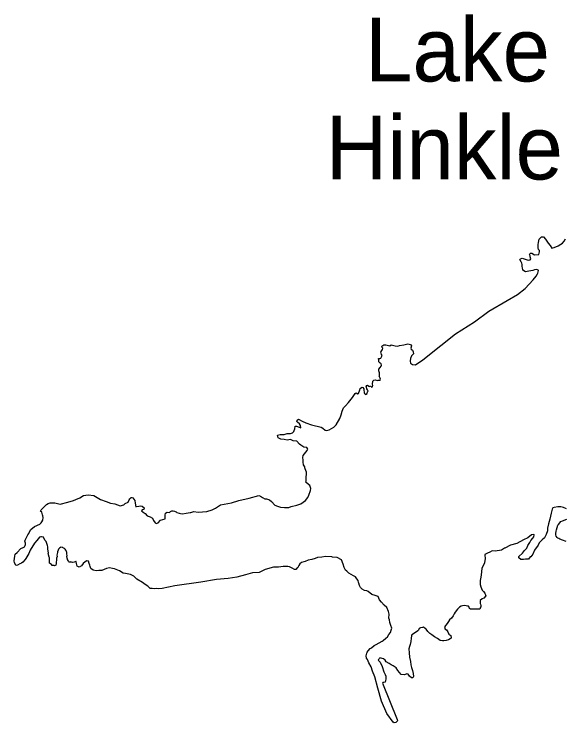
# Model space of a CAD drawing. Extents: x 1382482 to 1385815, y 1168351 to 1170484.
# Drawn here: x 1382760.2 to 1382805.8, y 1169935.8 to 1169994.4 of the extents above; entities that cross this region are included whole.
import ezdxf

# ---------------------------------------------------------------- set-up
doc = ezdxf.new("R2010")
doc.units = 0
doc.layers.add('9', color=7, linetype='Continuous')

msp = doc.modelspace()

# ---------------------------------------------------------------- linework, layer by layer
at = {"layer": '9'}
for points in [[(1382793.162, 1169965.416), (1382793.411, 1169965.4), (1382794.003, 1169965.81), (1382795.489, 1169966.995), (1382796.72, 1169967.945), (1382798.269, 1169968.951), (1382799.461, 1169969.84), (1382800.973, 1169970.715), (1382801.832, 1169971.199), (1382802.462, 1169971.71), (1382803.139, 1169972.411), (1382803.393, 1169972.725), (1382803.49, 1169972.927), (1382803.509, 1169972.977), (1382803.537, 1169973.068), (1382803.585, 1169973.178), (1382803.545, 1169973.228), (1382803.434, 1169973.266), (1382803.235, 1169973.233), (1382803.107, 1169973.181), (1382802.937, 1169973.168), (1382802.788, 1169973.145), (1382802.629, 1169973.113), (1382802.49, 1169973.08), (1382802.279, 1169973.217), (1382802.278, 1169973.267), (1382802.246, 1169973.396), (1382802.233, 1169973.556), (1382802.221, 1169973.676), (1382802.189, 1169973.806), (1382802.128, 1169973.895), (1382802.025, 1169974.103), (1382802.084, 1169974.144), (1382802.223, 1169974.196), (1382802.463, 1169974.13), (1382802.734, 1169974.045), (1382802.893, 1169974.077), (1382802.951, 1169974.168), (1382802.899, 1169974.327), (1382802.888, 1169974.397), (1382802.836, 1169974.516), (1382802.845, 1169974.576), (1382802.914, 1169974.628), (1382803.034, 1169974.62), (1382803.245, 1169974.483), (1382803.604, 1169974.519), (1382803.67, 1169974.72), (1382803.648, 1169974.83), (1382803.567, 1169974.938), (1382803.535, 1169975.058), (1382803.543, 1169975.178), (1382803.551, 1169975.328), (1382803.578, 1169975.509), (1382803.623, 1169975.769), (1382803.81, 1169975.972), (1382803.989, 1169975.965), (1382804.142, 1169975.788), (1382804.366, 1169975.462), (1382804.529, 1169975.244), (1382804.692, 1169975.047), (1382804.881, 1169975.09), (1382805.197, 1169975.225), (1382805.415, 1169975.359), (1382805.553, 1169975.451), (1382805.69, 1169975.613), (1382805.806, 1169975.805)], [(1382786.645, 1169960.229), (1382786.851, 1169960.442), (1382787.142, 1169960.957), (1382787.247, 1169961.249), (1382787.322, 1169961.55), (1382787.457, 1169961.842), (1382787.624, 1169962.005), (1382787.868, 1169962.279), (1382788.191, 1169962.704), (1382788.415, 1169963.028), (1382788.504, 1169963.079), (1382788.625, 1169962.981), (1382788.694, 1169963.032), (1382788.789, 1169963.324), (1382788.827, 1169963.425), (1382788.945, 1169963.527), (1382788.975, 1169963.537), (1382789.045, 1169963.518), (1382789.116, 1169963.409), (1382789.139, 1169963.27), (1382789.16, 1169963.17), (1382789.161, 1169963.1), (1382789.182, 1169963.021), (1382789.263, 1169962.952), (1382789.392, 1169963.014), (1382789.44, 1169963.155), (1382789.499, 1169963.206), (1382789.427, 1169963.315), (1382789.366, 1169963.414), (1382789.354, 1169963.533), (1382789.332, 1169963.613), (1382789.371, 1169963.694), (1382789.431, 1169963.705), (1382789.541, 1169963.636), (1382789.602, 1169963.607), (1382789.701, 1169963.649), (1382789.772, 1169963.54), (1382789.831, 1169963.581), (1382789.87, 1169963.692), (1382789.858, 1169963.802), (1382789.884, 1169964.052), (1382789.942, 1169964.133), (1382790.102, 1169964.146), (1382790.232, 1169964.098), (1382790.301, 1169964.119), (1382790.481, 1169964.132), (1382790.509, 1169964.212), (1382790.488, 1169964.302), (1382790.406, 1169964.461), (1382790.416, 1169964.461), (1382790.415, 1169964.481), (1382790.433, 1169964.611), (1382790.421, 1169964.731), (1382790.4, 1169964.811), (1382790.369, 1169964.89), (1382790.357, 1169964.98), (1382790.376, 1169965.04), (1382790.474, 1169965.182), (1382790.572, 1169965.274), (1382790.601, 1169965.324), (1382790.591, 1169965.364), (1382790.559, 1169965.463), (1382790.468, 1169965.542), (1382790.357, 1169965.64), (1382790.355, 1169965.78), (1382790.342, 1169965.92), (1382790.452, 1169965.922), (1382790.522, 1169965.933), (1382790.58, 1169966.044), (1382790.647, 1169966.175), (1382790.586, 1169966.254), (1382790.523, 1169966.453), (1382790.562, 1169966.494), (1382790.679, 1169966.656), (1382790.688, 1169966.756), (1382790.647, 1169966.835), (1382790.625, 1169966.945), (1382790.783, 1169967.037), (1382790.952, 1169967.04), (1382791.173, 1169966.984), (1382791.273, 1169966.955), (1382791.401, 1169967.037), (1382791.731, 1169966.963), (1382791.941, 1169966.926), (1382792.08, 1169966.979), (1382792.428, 1169967.044), (1382792.755, 1169967.14), (1382792.986, 1169967.073), (1382793.077, 1169966.955), (1382793.01, 1169966.774), (1382793.052, 1169966.695), (1382793.163, 1169966.596), (1382793.215, 1169966.457), (1382793.247, 1169966.308), (1382793.1, 1169966.165), (1382793.061, 1169966.125), (1382792.994, 1169965.914), (1382792.948, 1169965.723), (1382792.948, 1169965.703), (1382792.98, 1169965.533), (1382793.162, 1169965.416)], [(1382773.05, 1169953.194), (1382773.148, 1169953.256), (1382773.237, 1169953.317), (1382773.367, 1169953.319), (1382773.467, 1169953.291), (1382773.517, 1169953.272), (1382773.607, 1169953.243), (1382773.648, 1169953.184), (1382773.849, 1169953.117), (1382773.959, 1169953.089), (1382774.119, 1169953.062), (1382774.427, 1169953.117), (1382774.755, 1169953.182), (1382774.824, 1169953.193), (1382775.053, 1169953.257), (1382775.432, 1169953.223), (1382776.129, 1169953.275), (1382776.586, 1169953.402), (1382776.863, 1169953.537), (1382777.277, 1169953.824), (1382778.181, 1169953.979), (1382778.786, 1169954.189), (1382779.651, 1169954.373), (1382780.455, 1169954.586), (1382780.575, 1169954.548), (1382780.736, 1169954.421), (1382780.948, 1169954.304), (1382781.077, 1169954.306), (1382781.328, 1169954.24), (1382781.479, 1169954.103), (1382781.753, 1169953.797), (1382781.994, 1169953.711), (1382782.235, 1169953.625), (1382782.554, 1169953.591), (1382782.923, 1169953.587), (1382783.121, 1169953.67), (1382783.598, 1169953.778), (1382783.915, 1169953.913), (1382784.289, 1169954.189), (1382784.495, 1169954.413), (1382784.581, 1169954.624), (1382784.705, 1169954.996), (1382784.742, 1169955.177), (1382784.649, 1169955.405), (1382784.547, 1169955.504), (1382784.335, 1169955.7), (1382784.353, 1169955.81), (1382784.36, 1169956), (1382784.383, 1169956.461), (1382784.382, 1169956.511), (1382784.277, 1169956.799), (1382784.256, 1169956.879), (1382784.235, 1169956.949), (1382784.142, 1169957.137), (1382784.109, 1169957.357), (1382784.097, 1169957.506), (1382784.093, 1169957.736), (1382784.12, 1169957.887), (1382784.208, 1169958.028), (1382784.453, 1169958.312), (1382784.491, 1169958.413), (1382784.399, 1169958.571), (1382784.169, 1169958.598), (1382783.907, 1169958.763), (1382783.796, 1169958.842), (1382783.573, 1169959.088), (1382783.283, 1169959.123), (1382783.062, 1169959.209), (1382782.794, 1169959.175), (1382782.524, 1169959.211), (1382782.274, 1169959.247), (1382782.053, 1169959.353), (1382781.99, 1169959.572), (1382782.198, 1169959.625), (1382782.537, 1169959.641), (1382782.775, 1169959.705), (1382783.064, 1169959.72), (1382783.233, 1169959.762), (1382783.341, 1169959.894), (1382783.36, 1169959.954), (1382783.427, 1169960.106), (1382783.453, 1169960.326), (1382783.553, 1169960.308), (1382783.774, 1169960.231), (1382783.914, 1169960.174), (1382783.891, 1169960.373), (1382783.799, 1169960.512), (1382783.628, 1169960.649), (1382783.617, 1169960.659), (1382783.587, 1169960.718), (1382783.605, 1169960.829), (1382783.713, 1169960.89), (1382784.025, 1169960.725), (1382784.316, 1169960.59), (1382784.787, 1169960.438), (1382785.588, 1169960.241), (1382785.729, 1169960.143), (1382785.941, 1169959.987), (1382786.041, 1169959.969), (1382786.26, 1169960.022), (1382786.645, 1169960.229)], [(1382762.974, 1169950.468), (1382762.86, 1169950.786), (1382762.738, 1169950.894), (1382762.625, 1169951.143), (1382762.465, 1169951.18), (1382762.405, 1169951.169), (1382762.286, 1169951.137), (1382762.178, 1169951.015), (1382762.071, 1169950.873), (1382761.895, 1169950.651), (1382761.525, 1169950.084), (1382761.41, 1169949.792), (1382761.177, 1169949.389), (1382761.119, 1169949.288), (1382760.913, 1169949.074), (1382760.805, 1169949.002), (1382760.686, 1169948.95), (1382760.488, 1169948.837), (1382760.389, 1169948.816), (1382760.329, 1169948.835), (1382760.226, 1169949.023), (1382760.203, 1169949.193), (1382760.257, 1169949.563), (1382760.284, 1169949.744), (1382760.452, 1169949.877), (1382760.765, 1169950.202), (1382760.943, 1169950.305), (1382761.062, 1169950.347), (1382761.11, 1169950.448), (1382761.149, 1169950.548), (1382761.137, 1169950.658), (1382761.085, 1169950.817), (1382761.103, 1169950.908), (1382761.248, 1169951.18), (1382761.346, 1169951.332), (1382761.424, 1169951.443), (1382761.481, 1169951.594), (1382761.587, 1169951.786), (1382761.892, 1169952.041), (1382762.318, 1169952.228), (1382762.426, 1169952.329), (1382762.495, 1169952.411), (1382762.562, 1169952.562), (1382762.599, 1169952.762), (1382762.586, 1169952.912), (1382762.555, 1169952.992), (1382762.492, 1169953.221), (1382762.381, 1169953.289), (1382762.449, 1169953.4), (1382762.88, 1169953.847), (1382763.029, 1169953.929), (1382763.177, 1169953.992), (1382763.566, 1169953.988), (1382763.996, 1169953.885), (1382764.652, 1169954.046), (1382765.118, 1169954.184), (1382765.296, 1169954.267), (1382765.633, 1169954.392), (1382765.949, 1169954.598), (1382766.337, 1169954.654), (1382766.807, 1169954.582), (1382767.35, 1169954.271), (1382767.801, 1169954.098), (1382768.173, 1169953.944), (1382768.532, 1169953.9), (1382768.984, 1169953.727), (1382769.271, 1169953.832), (1382769.379, 1169953.924), (1382769.637, 1169954.038), (1382769.703, 1169954.239), (1382769.762, 1169954.32), (1382769.87, 1169954.422), (1382769.94, 1169954.423), (1382770.01, 1169954.394), (1382770.183, 1169954.167), (1382770.206, 1169953.958), (1382770.261, 1169953.648), (1382770.33, 1169953.69), (1382770.509, 1169953.712), (1382770.639, 1169953.725), (1382770.779, 1169953.697), (1382770.96, 1169953.56), (1382770.922, 1169953.439), (1382770.783, 1169953.397), (1382770.745, 1169953.326), (1382770.886, 1169953.199), (1382771.048, 1169953.091), (1382771.2, 1169952.914), (1382771.44, 1169952.838), (1382771.642, 1169952.711), (1382771.735, 1169952.513), (1382771.857, 1169952.325), (1382771.978, 1169952.286), (1382772.106, 1169952.339), (1382772.302, 1169952.562), (1382772.689, 1169952.668), (1382772.707, 1169952.789), (1382772.694, 1169952.968), (1382772.722, 1169953.119), (1382772.87, 1169953.211), (1382773.05, 1169953.194)], [(1382805.904, 1169953.484), (1382805.643, 1169953.6), (1382805.433, 1169953.647), (1382805.174, 1169953.652), (1382804.866, 1169953.597), (1382804.766, 1169953.576), (1382804.718, 1169953.455), (1382804.614, 1169953.143), (1382804.522, 1169952.642), (1382804.409, 1169952.25), (1382804.315, 1169951.888), (1382804.308, 1169951.678), (1382804.214, 1169951.356), (1382804.068, 1169951.084), (1382803.891, 1169950.931), (1382803.627, 1169950.667), (1382803.56, 1169950.476), (1382803.257, 1169950.061), (1382803.113, 1169949.748), (1382802.947, 1169949.525), (1382802.897, 1169949.515), (1382802.761, 1169949.332), (1382802.701, 1169949.331), (1382802.511, 1169949.328), (1382802.332, 1169949.305), (1382802.113, 1169949.292), (1382801.961, 1169949.449), (1382801.949, 1169949.559), (1382802.254, 1169949.834), (1382802.43, 1169950.037), (1382802.597, 1169950.24), (1382802.693, 1169950.451), (1382802.868, 1169950.714), (1382802.955, 1169950.866), (1382803.102, 1169951.058), (1382803.19, 1169951.17), (1382803.207, 1169951.33), (1382803.177, 1169951.359), (1382803.008, 1169951.347), (1382802.682, 1169951.101), (1382802.326, 1169950.935), (1382801.783, 1169950.626), (1382801.257, 1169950.478), (1382800.792, 1169950.24), (1382800.752, 1169950.229), (1382800.526, 1169950.076), (1382799.998, 1169949.997), (1382799.749, 1169950.013), (1382799.541, 1169949.919), (1382799.353, 1169949.836), (1382799.146, 1169949.713), (1382799.127, 1169949.653), (1382799.171, 1169949.393), (1382799.107, 1169949.032), (1382798.885, 1169948.549), (1382798.824, 1169948.027), (1382798.807, 1169947.847), (1382798.761, 1169947.566), (1382798.757, 1169947.236)], [(1382805.858, 1169950.793), (1382805.567, 1169950.909), (1382805.346, 1169950.975), (1382805.266, 1169951.024), (1382805.175, 1169951.072), (1382805.125, 1169951.121), (1382805.043, 1169951.22), (1382805.021, 1169951.35), (1382805.02, 1169951.45), (1382805.047, 1169951.63), (1382805.065, 1169951.74), (1382805.132, 1169951.932), (1382805.178, 1169952.132), (1382805.237, 1169952.183), (1382805.413, 1169952.446), (1382805.551, 1169952.499), (1382805.918, 1169952.645)], [(1382780.971, 1169948.464), (1382780.477, 1169948.236), (1382779.929, 1169948.187), (1382779.343, 1169948.037), (1382778.609, 1169947.845), (1382777.893, 1169947.723), (1382776.927, 1169947.647), (1382775.654, 1169947.426), (1382773.506, 1169947.131), (1382772.443, 1169946.894), (1382772.114, 1169946.868), (1382771.944, 1169946.905), (1382771.785, 1169946.883), (1382771.625, 1169946.89), (1382771.466, 1169946.897), (1382771.263, 1169947.084), (1382771.042, 1169947.221), (1382770.81, 1169947.407), (1382770.337, 1169947.669), (1382770.094, 1169947.915), (1382769.822, 1169948.071), (1382769.412, 1169948.144), (1382769.232, 1169948.181), (1382768.93, 1169948.366), (1382768.77, 1169948.413), (1382768.509, 1169948.519), (1382768.349, 1169948.546), (1382768.098, 1169948.612), (1382767.85, 1169948.548), (1382767.464, 1169948.382), (1382767.205, 1169948.388), (1382766.996, 1169948.374), (1382766.726, 1169948.42), (1382766.534, 1169948.547), (1382766.482, 1169948.716), (1382766.45, 1169948.825), (1382766.418, 1169948.975), (1382766.355, 1169949.154), (1382766.205, 1169949.191), (1382766.087, 1169949.109), (1382765.899, 1169948.976), (1382765.763, 1169948.774), (1382765.575, 1169948.671), (1382765.414, 1169948.758), (1382765.361, 1169948.957), (1382765.329, 1169949.137), (1382765.308, 1169949.146), (1382765.249, 1169949.106), (1382765.17, 1169949.084), (1382765.031, 1169949.052), (1382764.891, 1169949.1), (1382764.921, 1169949.07), (1382764.841, 1169949.079), (1382764.771, 1169949.088), (1382764.761, 1169949.087), (1382764.7, 1169949.136), (1382764.669, 1169949.206), (1382764.628, 1169949.295), (1382764.618, 1169949.325), (1382764.577, 1169949.404), (1382764.564, 1169949.554), (1382764.583, 1169949.625), (1382764.571, 1169949.744), (1382764.559, 1169949.874), (1382764.528, 1169949.964), (1382764.517, 1169950.014), (1382764.497, 1169950.043), (1382764.476, 1169950.063), (1382764.425, 1169950.162), (1382764.354, 1169950.211), (1382764.274, 1169950.25), (1382764.224, 1169950.279), (1382764.173, 1169950.298), (1382764.044, 1169950.316), (1382764.024, 1169950.305), (1382763.945, 1169950.244), (1382763.877, 1169950.163), (1382763.838, 1169950.082), (1382763.8, 1169949.932), (1382763.801, 1169949.882), (1382763.745, 1169949.661), (1382763.767, 1169949.541), (1382763.709, 1169949.41), (1382763.692, 1169949.26), (1382763.665, 1169949.059), (1382763.687, 1169948.93), (1382763.648, 1169948.839), (1382763.55, 1169948.778), (1382763.5, 1169948.797), (1382763.35, 1169948.814), (1382763.279, 1169948.883), (1382763.137, 1169949.001), (1382763.124, 1169949.221), (1382763.133, 1169949.261), (1382763.131, 1169949.431), (1382763.09, 1169949.5), (1382763.025, 1169949.789), (1382763.044, 1169949.849), (1382762.989, 1169950.158), (1382762.976, 1169950.348), (1382762.974, 1169950.468)], [(1382790.485, 1169940.8), (1382790.631, 1169940.442), (1382790.777, 1169940.024), (1382790.89, 1169939.806), (1382790.942, 1169939.657), (1382790.936, 1169939.417), (1382790.908, 1169939.306), (1382790.88, 1169939.166), (1382790.88, 1169939.156), (1382790.781, 1169939.144), (1382790.721, 1169939.133), (1382790.712, 1169939.123), (1382790.672, 1169939.072), (1382791.887, 1169936.082), (1382791.899, 1169935.952), (1382791.771, 1169935.83), (1382791.642, 1169935.798), (1382791.542, 1169935.846), (1382791.032, 1169936.568), (1382790.586, 1169937.601), (1382790.29, 1169938.676), (1382790.036, 1169939.592), (1382789.849, 1169940.059), (1382789.733, 1169940.437), (1382789.539, 1169940.764), (1382789.425, 1169941.032), (1382789.343, 1169941.151), (1382789.31, 1169941.33), (1382789.387, 1169941.552), (1382789.405, 1169941.632), (1382789.493, 1169941.753), (1382789.649, 1169941.956), (1382789.748, 1169942.008), (1382789.975, 1169942.191), (1382790.153, 1169942.264), (1382790.39, 1169942.398), (1382790.637, 1169942.542), (1382790.736, 1169942.594), (1382790.952, 1169942.807), (1382791.089, 1169942.92), (1382791.196, 1169943.112), (1382791.343, 1169943.264), (1382791.4, 1169943.445), (1382791.437, 1169943.626), (1382791.364, 1169943.844), (1382791.29, 1169944.083), (1382791.246, 1169944.322), (1382791.194, 1169944.452), (1382791.219, 1169944.772), (1382791.176, 1169944.991), (1382791.041, 1169945.319), (1382790.819, 1169945.516), (1382790.585, 1169945.762), (1382790.423, 1169945.959), (1382790.308, 1169946.247), (1382790.068, 1169946.323), (1382789.777, 1169946.409), (1382789.484, 1169946.654), (1382789.364, 1169946.712), (1382789.184, 1169946.749), (1382788.983, 1169946.836), (1382788.841, 1169946.983), (1382788.768, 1169947.162), (1382788.706, 1169947.331), (1382788.675, 1169947.411), (1382788.672, 1169947.561), (1382788.551, 1169947.689), (1382788.428, 1169947.857), (1382788.277, 1169947.944), (1382788.086, 1169948.051), (1382787.885, 1169948.168), (1382787.713, 1169948.325), (1382787.602, 1169948.423), (1382787.509, 1169948.631), (1382787.424, 1169948.92), (1382787.279, 1169949.278), (1382786.927, 1169949.472), (1382786.548, 1169949.506), (1382786.487, 1169949.525), (1382785.969, 1169949.536), (1382785.651, 1169949.491), (1382785.292, 1169949.455), (1382785.094, 1169949.372), (1382784.826, 1169949.287), (1382784.528, 1169949.233), (1382784.28, 1169949.138), (1382784.161, 1169949.116), (1382783.973, 1169949.053), (1382783.845, 1169948.941), (1382783.738, 1169948.799), (1382783.68, 1169948.649), (1382783.611, 1169948.607), (1382783.513, 1169948.476), (1382783.384, 1169948.474), (1382783.212, 1169948.591), (1382782.991, 1169948.697), (1382782.852, 1169948.715), (1382782.443, 1169948.708), (1382782.065, 1169948.662), (1382781.666, 1169948.655), (1382780.971, 1169948.464)], [(1382798.757, 1169947.236), (1382798.81, 1169947.037), (1382798.914, 1169946.769), (1382799.015, 1169946.65), (1382799.127, 1169946.512), (1382799.21, 1169946.294), (1382799.054, 1169946.111), (1382798.905, 1169946.059), (1382798.748, 1169945.906), (1382798.762, 1169945.666), (1382798.783, 1169945.597), (1382798.804, 1169945.497), (1382798.806, 1169945.367), (1382798.777, 1169945.346), (1382798.709, 1169945.205), (1382798.45, 1169945.191), (1382798.291, 1169945.188), (1382798.101, 1169945.195), (1382797.952, 1169945.203), (1382797.861, 1169945.261), (1382797.83, 1169945.361), (1382797.778, 1169945.45), (1382797.708, 1169945.449), (1382797.579, 1169945.467), (1382797.459, 1169945.485), (1382797.299, 1169945.482), (1382797.18, 1169945.45), (1382797.052, 1169945.358), (1382796.865, 1169945.195), (1382796.67, 1169944.942), (1382796.602, 1169944.811), (1382796.505, 1169944.639), (1382796.379, 1169944.457), (1382796.221, 1169944.314), (1382796.134, 1169944.183), (1382796.007, 1169944.001), (1382795.812, 1169943.747), (1382795.823, 1169943.678), (1382795.835, 1169943.558), (1382795.955, 1169943.49), (1382796.068, 1169943.322), (1382796.17, 1169943.133), (1382796.312, 1169943.016), (1382796.365, 1169942.836), (1382796.345, 1169942.786), (1382796.266, 1169942.735), (1382796.138, 1169942.653), (1382795.94, 1169942.599), (1382795.75, 1169942.586), (1382795.631, 1169942.584), (1382795.441, 1169942.611), (1382795.209, 1169942.767), (1382794.968, 1169942.904), (1382794.756, 1169943.06), (1382794.584, 1169943.187), (1382794.554, 1169943.207), (1382794.432, 1169943.345), (1382794.28, 1169943.542), (1382794.199, 1169943.601), (1382794.068, 1169943.709), (1382793.978, 1169943.687), (1382793.809, 1169943.655), (1382793.701, 1169943.583), (1382793.643, 1169943.452), (1382793.604, 1169943.391), (1382793.229, 1169943.145), (1382793.111, 1169943.063), (1382793.062, 1169942.982), (1382793.035, 1169942.802), (1382793.02, 1169942.531), (1382792.954, 1169942.26), (1382792.917, 1169942.12), (1382792.84, 1169941.908), (1382792.885, 1169941.589), (1382792.911, 1169941.23), (1382792.977, 1169940.861), (1382793.011, 1169940.581), (1382793.074, 1169940.372), (1382793.148, 1169940.133), (1382793.212, 1169939.864), (1382793.236, 1169939.615), (1382793.188, 1169939.514), (1382793.068, 1169939.512), (1382792.906, 1169939.659), (1382792.794, 1169939.807), (1382792.684, 1169939.846), (1382792.496, 1169939.763), (1382792.226, 1169939.798), (1382791.952, 1169940.124), (1382791.789, 1169940.351), (1382791.557, 1169940.497), (1382791.376, 1169940.604), (1382791.225, 1169940.702), (1382790.983, 1169940.828), (1382790.881, 1169940.976), (1382790.75, 1169941.084), (1382790.439, 1169941.179), (1382790.41, 1169941.128), (1382790.312, 1169941.017), (1382790.353, 1169940.947), (1382790.485, 1169940.8)]]:
    msp.add_lwpolyline(points, dxfattribs=at)

# ---------------------------------------------------------------- texts
for s, p in [('Lake', (1382789.219, 1169988.818)), ('Hinkle', (1382785.982, 1169980.715))]:
    msp.add_text(s, height=5.28, dxfattribs=at).set_placement(p)

doc.saveas('drawing.dxf')
